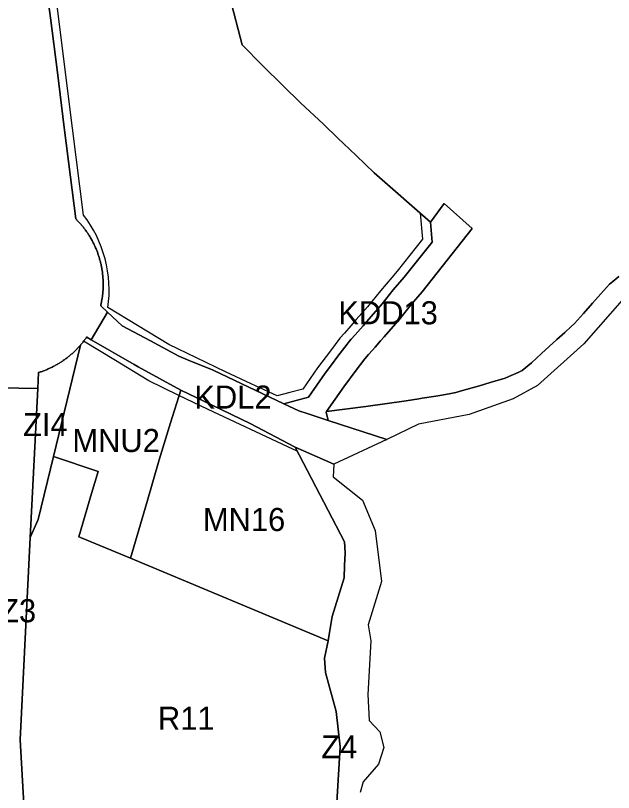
# Model space of a CAD drawing. Extents: x 7439486 to 7443435, y 5551288 to 5554556.
# Drawn here: x 7440797.2 to 7441056.3, y 5551897.3 to 5552233.9 of the extents above; entities that cross this region are included whole.
import ezdxf

# ---------------------------------------------------------------- set-up
doc = ezdxf.new("R2010")
doc.units = 0
for name, color, linetype in [('linie_rozgraniczajace', 7, 'Continuous'), ('linie_zabudowy_nieprzekraczalne', 7, 'Continuous'), ('oznaczenia_przeznaczen', 7, 'Continuous')]:
    doc.layers.add(name, color=color, linetype=linetype)

msp = doc.modelspace()

# ---------------------------------------------------------------- linework, layer by layer
at = {"layer": 'linie_rozgraniczajace'}
for points in [[(7441199.76, 5553005.69), (7441030.31, 5552730.01), (7441018.76, 5552711.22), (7440937.87, 5552579.63), (7440872.68, 5552522.16), (7440861.3, 5552510.94), (7440860.32, 5552509.94), (7440850.87, 5552500.24), (7440841.01, 5552490.47), (7440831.14, 5552480.7), (7440822.38, 5552472.46), (7440813.62, 5552464.22), (7440805.16, 5552456.78), (7440796.71, 5552449.34), (7440788.29, 5552442.28), (7440784.09, 5552438.75), (7440811.19, 5552387.81), (7440863.47, 5552293.77), (7440866.42, 5552287.9), (7440881.12, 5552260.61), (7440890.03, 5552241.86), (7440895.39, 5552221.28), (7440904.26, 5552212.34)], [(7440831.45, 5552134.34), (7440831.28, 5552134.7), (7440831.1, 5552135.06), (7440830.92, 5552135.42), (7440830.74, 5552135.78), (7440830.56, 5552136.13), (7440830.37, 5552136.48), (7440830.17, 5552136.83), (7440829.98, 5552137.18), (7440829.78, 5552137.53), (7440829.58, 5552137.87), (7440829.37, 5552138.22), (7440829.16, 5552138.56), (7440828.95, 5552138.9), (7440828.73, 5552139.23), (7440828.51, 5552139.57), (7440828.29, 5552139.9), (7440828.06, 5552140.23), (7440827.83, 5552140.56), (7440827.6, 5552140.88), (7440827.36, 5552141.2), (7440827.12, 5552141.52), (7440826.88, 5552141.84), (7440826.63, 5552142.16), (7440826.38, 5552142.47), (7440826.13, 5552142.78), (7440825.88, 5552143.09), (7440825.62, 5552143.4), (7440825.36, 5552143.7), (7440825.09, 5552144), (7440824.82, 5552144.3), (7440824.55, 5552144.59), (7440824.28, 5552144.88), (7440824, 5552145.17), (7440823.73, 5552145.46), (7440823.44, 5552145.74), (7440823.33, 5552145.85), (7440821.06, 5552163.89), (7440818.35, 5552185.39), (7440815.35, 5552209.18), (7440812.35, 5552232.97), (7440810.86, 5552244.81)], [(7440810.86, 5552244.81), (7440812.35, 5552232.97), (7440815.35, 5552209.18), (7440818.35, 5552185.39), (7440821.06, 5552163.89), (7440823.33, 5552145.85), (7440823.44, 5552145.74), (7440823.73, 5552145.46), (7440824, 5552145.17), (7440824.28, 5552144.88), (7440824.55, 5552144.59), (7440824.82, 5552144.3), (7440825.09, 5552144), (7440825.36, 5552143.7), (7440825.62, 5552143.4), (7440825.88, 5552143.09), (7440826.13, 5552142.78), (7440826.38, 5552142.47), (7440826.63, 5552142.16), (7440826.88, 5552141.84), (7440827.12, 5552141.52), (7440827.36, 5552141.2), (7440827.6, 5552140.88), (7440827.83, 5552140.56), (7440828.06, 5552140.23), (7440828.29, 5552139.9), (7440828.51, 5552139.57), (7440828.73, 5552139.23), (7440828.95, 5552138.9), (7440829.16, 5552138.56), (7440829.37, 5552138.22), (7440829.58, 5552137.87), (7440829.78, 5552137.53), (7440829.98, 5552137.18), (7440830.17, 5552136.83), (7440830.37, 5552136.48), (7440830.56, 5552136.13), (7440830.74, 5552135.78), (7440830.92, 5552135.42), (7440831.1, 5552135.06), (7440831.28, 5552134.7), (7440831.45, 5552134.34), (7440831.62, 5552133.98), (7440831.78, 5552133.61), (7440831.94, 5552133.25), (7440832.1, 5552132.88), (7440832.25, 5552132.51), (7440832.4, 5552132.14)], [(7441011, 5552077.52), (7441009.36, 5552076.79), (7441002.84, 5552074.87), (7440998.26, 5552073.46), (7440996.72, 5552073.03), (7440990.85, 5552071.38), (7440987.98, 5552070.61), (7440985.82, 5552070.1), (7440981.94, 5552069.36), (7440979.31, 5552068.97), (7440973.47, 5552068.1), (7440971.96, 5552067.8), (7440966.51, 5552067.03), (7440949.03, 5552064.54), (7440931.92, 5552062.32), (7440939.46, 5552073.05), (7440944.87, 5552080.29), (7440948.61, 5552085.24), (7440950.22, 5552087.08), (7440951.85, 5552088.95), (7440953.02, 5552090.28), (7440955.35, 5552092.94), (7440956.93, 5552094.75), (7440963.81, 5552102.61), (7440968.61, 5552108.67), (7440973.37, 5552114.18), (7440995.11, 5552141.6), (7440982.93, 5552152.49), (7440976.95, 5552144.42), (7440952.61, 5552165.83), (7440944.83, 5552173.23), (7440939.3, 5552178.5), (7440937.05, 5552180.63), (7440930.6, 5552186.78), (7440920.74, 5552196.16), (7440913.12, 5552203.41), (7440904.26, 5552212.34), (7440895.39, 5552221.28), (7440890.03, 5552241.86)], [(7440904.26, 5552212.34), (7440913.12, 5552203.41), (7440920.74, 5552196.16), (7440930.6, 5552186.78), (7440937.05, 5552180.63), (7440939.3, 5552178.5), (7440944.83, 5552173.23), (7440952.61, 5552165.83), (7440976.95, 5552144.42), (7440977.69, 5552135.72), (7440965.67, 5552120.55), (7440960.9, 5552115.04), (7440956.12, 5552109.01), (7440949.41, 5552101.34), (7440947.83, 5552099.53), (7440945.5, 5552096.87), (7440944.33, 5552095.53), (7440942.7, 5552093.67), (7440941.77, 5552092.62), (7440940.85, 5552091.56), (7440938.86, 5552088.93), (7440936.87, 5552086.3), (7440934.12, 5552082.61), (7440931.36, 5552078.92), (7440924.12, 5552068.62), (7440913.44, 5552065.74), (7440882.85, 5552080.29), (7440871.72, 5552084.77), (7440867.98, 5552086.26), (7440855.68, 5552092.9), (7440843.38, 5552099.54), (7440837.05, 5552105.45), (7440834.14, 5552108.17), (7440834.23, 5552108.56), (7440834.31, 5552108.95), (7440834.39, 5552109.34), (7440834.47, 5552109.73), (7440834.55, 5552110.13), (7440834.62, 5552110.52), (7440834.69, 5552110.92), (7440834.75, 5552111.31), (7440834.81, 5552111.71), (7440834.86, 5552112.1), (7440834.91, 5552112.5), (7440834.96, 5552112.9), (7440835, 5552113.29), (7440835.04, 5552113.69), (7440835.08, 5552114.09), (7440835.11, 5552114.49), (7440835.13, 5552114.89), (7440835.16, 5552115.29), (7440835.18, 5552115.69), (7440835.19, 5552116.09), (7440835.2, 5552116.49), (7440835.21, 5552116.89), (7440835.21, 5552117.29), (7440835.21, 5552117.69), (7440835.21, 5552118.09), (7440835.2, 5552118.49), (7440835.19, 5552118.89), (7440835.17, 5552119.29), (7440835.15, 5552119.69), (7440835.12, 5552120.09), (7440835.09, 5552120.49), (7440835.06, 5552120.88), (7440835.02, 5552121.28), (7440834.98, 5552121.68), (7440834.94, 5552122.08), (7440834.89, 5552122.48), (7440834.84, 5552122.87), (7440834.78, 5552123.27), (7440834.72, 5552123.66), (7440834.65, 5552124.06), (7440834.59, 5552124.45), (7440834.51, 5552124.85), (7440834.44, 5552125.24), (7440834.36, 5552125.63), (7440834.27, 5552126.02), (7440834.18, 5552126.41), (7440834.09, 5552126.8), (7440834, 5552127.19), (7440833.9, 5552127.58), (7440833.79, 5552127.96), (7440833.68, 5552128.35), (7440833.57, 5552128.73), (7440833.46, 5552129.12), (7440833.34, 5552129.5), (7440833.22, 5552129.88), (7440833.09, 5552130.26), (7440832.96, 5552130.64), (7440832.82, 5552131.01), (7440832.69, 5552131.39), (7440832.55, 5552131.76), (7440832.4, 5552132.14), (7440832.25, 5552132.51), (7440832.1, 5552132.88), (7440831.94, 5552133.25), (7440831.78, 5552133.61), (7440831.62, 5552133.98), (7440831.45, 5552134.34)], [(7440832.4, 5552132.14), (7440832.55, 5552131.76), (7440832.69, 5552131.39), (7440832.82, 5552131.01), (7440832.96, 5552130.64), (7440833.09, 5552130.26), (7440833.22, 5552129.88), (7440833.34, 5552129.5), (7440833.46, 5552129.12), (7440833.57, 5552128.73), (7440833.68, 5552128.35), (7440833.79, 5552127.96), (7440833.9, 5552127.58), (7440834, 5552127.19), (7440834.09, 5552126.8), (7440834.18, 5552126.41), (7440834.27, 5552126.02), (7440834.36, 5552125.63), (7440834.44, 5552125.24), (7440834.51, 5552124.85), (7440834.59, 5552124.45), (7440834.65, 5552124.06), (7440834.72, 5552123.66), (7440834.78, 5552123.27), (7440834.84, 5552122.87), (7440834.89, 5552122.48), (7440834.94, 5552122.08), (7440834.98, 5552121.68), (7440835.02, 5552121.28), (7440835.06, 5552120.88), (7440835.09, 5552120.49), (7440835.12, 5552120.09), (7440835.15, 5552119.69), (7440835.17, 5552119.29), (7440835.19, 5552118.89), (7440835.2, 5552118.49), (7440835.21, 5552118.09), (7440835.21, 5552117.69), (7440835.21, 5552117.29), (7440835.21, 5552116.89), (7440835.2, 5552116.49), (7440835.19, 5552116.09), (7440835.18, 5552115.69), (7440835.16, 5552115.29), (7440835.13, 5552114.89), (7440835.11, 5552114.49), (7440835.08, 5552114.09), (7440835.04, 5552113.69), (7440835, 5552113.29), (7440834.96, 5552112.9), (7440834.91, 5552112.5), (7440834.86, 5552112.1), (7440834.81, 5552111.71), (7440834.75, 5552111.31), (7440834.69, 5552110.92), (7440834.62, 5552110.52), (7440834.55, 5552110.13), (7440834.47, 5552109.73), (7440834.39, 5552109.34), (7440834.31, 5552108.95), (7440834.23, 5552108.56), (7440834.14, 5552108.17), (7440837.05, 5552105.45), (7440830, 5552093.47), (7440828.06, 5552094.58), (7440828.01, 5552094.51), (7440827.78, 5552094.18), (7440827.55, 5552093.86), (7440827.32, 5552093.54), (7440827.08, 5552093.22), (7440826.84, 5552092.9), (7440826.59, 5552092.59), (7440826.34, 5552092.28), (7440826.09, 5552091.97), (7440825.84, 5552091.66), (7440825.58, 5552091.36), (7440825.32, 5552091.05), (7440825.08, 5552090.78), (7440824.81, 5552090.48), (7440824.54, 5552090.18), (7440824.27, 5552089.89), (7440824, 5552089.6), (7440823.72, 5552089.32), (7440823.44, 5552089.04), (7440823.16, 5552088.76), (7440822.87, 5552088.48), (7440822.58, 5552088.2), (7440822.29, 5552087.93), (7440822, 5552087.66), (7440821.7, 5552087.4), (7440821.4, 5552087.14), (7440821.1, 5552086.88), (7440820.79, 5552086.62), (7440820.49, 5552086.37), (7440820.18, 5552086.12), (7440819.86, 5552085.87), (7440819.55, 5552085.62), (7440819.23, 5552085.38), (7440818.91, 5552085.15), (7440818.59, 5552084.91)], [(7440931.77, 5552062.12), (7440931.92, 5552062.32), (7440949.03, 5552064.54), (7440966.51, 5552067.03), (7440971.96, 5552067.8), (7440973.47, 5552068.1), (7440979.31, 5552068.97), (7440981.94, 5552069.36), (7440985.82, 5552070.1), (7440987.98, 5552070.61), (7440990.85, 5552071.38), (7440996.72, 5552073.03), (7440998.26, 5552073.46), (7441002.84, 5552074.87), (7441009.36, 5552076.79), (7441011, 5552077.52), (7441015.07, 5552079.32), (7441016.77, 5552080.14), (7441020.72, 5552083.51), (7441025.11, 5552087.52), (7441031.76, 5552093.58), (7441035.28, 5552096.63), (7441038.02, 5552099.21), (7441039.36, 5552100.48), (7441043.29, 5552104.85), (7441047.16, 5552109.27), (7441053.28, 5552116.09), (7441054.6, 5552117.56), (7441056.02, 5552118.7), (7441058.67, 5552120.82)], [(7441058.67, 5552120.82), (7441056.02, 5552118.7), (7441054.6, 5552117.56), (7441053.28, 5552116.09), (7441047.16, 5552109.27), (7441043.29, 5552104.85), (7441039.36, 5552100.48), (7441038.02, 5552099.21), (7441035.28, 5552096.63), (7441031.76, 5552093.58), (7441025.11, 5552087.52), (7441020.72, 5552083.51), (7441016.77, 5552080.14), (7441015.07, 5552079.32), (7441011, 5552077.52)], [(7441061.04, 5552111.8), (7441043.46, 5552091.62), (7441023.35, 5552073.57), (7441012.83, 5552067.78), (7440993.72, 5552061), (7440971.79, 5552056.9), (7440958.03, 5552050.25), (7440932.72, 5552058.49), (7440931.77, 5552062.12)], [(7440818.59, 5552084.91), (7440818.27, 5552084.68), (7440817.94, 5552084.45), (7440817.61, 5552084.23), (7440817.28, 5552084.01), (7440816.95, 5552083.79), (7440816.61, 5552083.57), (7440816.27, 5552083.36), (7440815.93, 5552083.15), (7440815.59, 5552082.95), (7440815.25, 5552082.75), (7440814.9, 5552082.55), (7440814.56, 5552082.36), (7440814.21, 5552082.17), (7440813.85, 5552081.98), (7440813.5, 5552081.8), (7440813.15, 5552081.62), (7440812.79, 5552081.44), (7440812.43, 5552081.27), (7440812.07, 5552081.1), (7440811.71, 5552080.93), (7440811.34, 5552080.77), (7440810.98, 5552080.61), (7440810.61, 5552080.46), (7440810.24, 5552080.31), (7440809.87, 5552080.16), (7440809.5, 5552080.02), (7440809.13, 5552079.88), (7440808.75, 5552079.74), (7440808.38, 5552079.61), (7440808, 5552079.48), (7440807.62, 5552079.36), (7440807.24, 5552079.23), (7440806.89, 5552072.31), (7440781.88, 5552072.73)], [(7440936.43, 5551892.9), (7440937.85, 5551917.06), (7440936.16, 5551932.33), (7440931.56, 5551949.2), (7440931.14, 5551955.45), (7440932.72, 5551962.93), (7440933.18, 5551965.79), (7440934.41, 5551973.55), (7440937.01, 5551981.91), (7440939.61, 5551990.27), (7440939.79, 5551995.65), (7440939.98, 5552001.04), (7440939.86, 5552003.75), (7440939.77, 5552005.9), (7440929.08, 5552026.38), (7440918.39, 5552046.87), (7440935.14, 5552039.49), (7440934.83, 5552034.11), (7440947.52, 5552023.89), (7440953.08, 5552010.74), (7440955.78, 5551988.68), (7440950.01, 5551969.87), (7440951.13, 5551962.97), (7440949.92, 5551939.68), (7440950.41, 5551928.43), (7440955.1, 5551923.49), (7440956.78, 5551916.8), (7440954.45, 5551909.61), (7440947.8, 5551901.92), (7440946.49, 5551897.2)], [(7440800.76, 5551892.23), (7440799.21, 5551920.11), (7440803.64, 5552007.76), (7440807.02, 5552015.57), (7440813.63, 5552042.85), (7440833.07, 5552036.36), (7440830.18, 5552026.84), (7440824.66, 5552008.11), (7440825.35, 5552007.82), (7440825.36, 5552007.82), (7440847.05, 5551998.75), (7440932.72, 5551962.93), (7440931.14, 5551955.45), (7440931.56, 5551949.2), (7440936.16, 5551932.33), (7440937.85, 5551917.06), (7440936.43, 5551892.9)]]:
    msp.add_lwpolyline(points, dxfattribs=at)
for points in [[(7440913.44, 5552065.74), (7440924.12, 5552068.62), (7440931.36, 5552078.92), (7440934.12, 5552082.61), (7440936.87, 5552086.3), (7440938.86, 5552088.93), (7440940.85, 5552091.56), (7440941.77, 5552092.62), (7440942.7, 5552093.67), (7440944.33, 5552095.53), (7440945.5, 5552096.87), (7440947.83, 5552099.53), (7440949.41, 5552101.34), (7440956.12, 5552109.01), (7440960.9, 5552115.04), (7440965.67, 5552120.55), (7440977.69, 5552135.72), (7440976.95, 5552144.42), (7440982.93, 5552152.49), (7440995.11, 5552141.6), (7440973.37, 5552114.18), (7440968.61, 5552108.67), (7440963.81, 5552102.61), (7440956.93, 5552094.75), (7440955.35, 5552092.94), (7440953.02, 5552090.28), (7440951.85, 5552088.95), (7440950.22, 5552087.08), (7440948.61, 5552085.24), (7440944.87, 5552080.29), (7440939.46, 5552073.05), (7440931.92, 5552062.32), (7440931.77, 5552062.12), (7440932.72, 5552058.49), (7440923.55, 5552061.48), (7440919.93, 5552062.65)], [(7440830, 5552093.47), (7440837.05, 5552105.45), (7440843.38, 5552099.54), (7440855.68, 5552092.9), (7440867.98, 5552086.26), (7440871.72, 5552084.77), (7440882.85, 5552080.29), (7440913.44, 5552065.74), (7440919.93, 5552062.65), (7440923.55, 5552061.48), (7440932.72, 5552058.49), (7440958.03, 5552050.25), (7440935.14, 5552039.49), (7440918.39, 5552046.87), (7440898.89, 5552057.14), (7440882.45, 5552065.06), (7440868.85, 5552071.61), (7440850.42, 5552081.71), (7440848.6, 5552082.76)], [(7440813.63, 5552042.85), (7440825.32, 5552091.05), (7440825.58, 5552091.36), (7440825.84, 5552091.66), (7440826.09, 5552091.97), (7440826.34, 5552092.28), (7440826.59, 5552092.59), (7440826.84, 5552092.9), (7440827.08, 5552093.22), (7440827.32, 5552093.54), (7440827.55, 5552093.86), (7440827.78, 5552094.18), (7440828.01, 5552094.51), (7440828.06, 5552094.58), (7440830, 5552093.47), (7440848.6, 5552082.76), (7440850.42, 5552081.71), (7440868.85, 5552071.61), (7440864.43, 5552057.43), (7440860, 5552043.26), (7440859.4, 5552041.35), (7440854.2, 5552023.4), (7440847.05, 5551998.75), (7440825.36, 5552007.82), (7440825.35, 5552007.82), (7440824.66, 5552008.11), (7440830.18, 5552026.84), (7440833.07, 5552036.36)], [(7440803.64, 5552007.76), (7440806.89, 5552072.31), (7440807.24, 5552079.23), (7440807.62, 5552079.36), (7440808, 5552079.48), (7440808.38, 5552079.61), (7440808.75, 5552079.74), (7440809.13, 5552079.88), (7440809.5, 5552080.02), (7440809.87, 5552080.16), (7440810.24, 5552080.31), (7440810.61, 5552080.46), (7440810.98, 5552080.61), (7440811.34, 5552080.77), (7440811.71, 5552080.93), (7440812.07, 5552081.1), (7440812.43, 5552081.27), (7440812.79, 5552081.44), (7440813.15, 5552081.62), (7440813.5, 5552081.8), (7440813.85, 5552081.98), (7440814.21, 5552082.17), (7440814.56, 5552082.36), (7440814.9, 5552082.55), (7440815.25, 5552082.75), (7440815.59, 5552082.95), (7440815.93, 5552083.15), (7440816.27, 5552083.36), (7440816.61, 5552083.57), (7440816.95, 5552083.79), (7440817.28, 5552084.01), (7440817.61, 5552084.23), (7440817.94, 5552084.45), (7440818.27, 5552084.68), (7440818.59, 5552084.91), (7440818.91, 5552085.15), (7440819.23, 5552085.38), (7440819.55, 5552085.62), (7440819.86, 5552085.87), (7440820.18, 5552086.12), (7440820.49, 5552086.37), (7440820.79, 5552086.62), (7440821.1, 5552086.88), (7440821.4, 5552087.14), (7440821.7, 5552087.4), (7440822, 5552087.66), (7440822.29, 5552087.93), (7440822.58, 5552088.2), (7440822.87, 5552088.48), (7440823.16, 5552088.76), (7440823.44, 5552089.04), (7440823.72, 5552089.32), (7440824, 5552089.6), (7440824.27, 5552089.89), (7440824.54, 5552090.18), (7440824.81, 5552090.48), (7440825.08, 5552090.78), (7440825.32, 5552091.05), (7440813.63, 5552042.85), (7440807.02, 5552015.57)], [(7440774.18, 5551920.04), (7440781.88, 5552072.73), (7440806.89, 5552072.31), (7440803.64, 5552007.76), (7440799.21, 5551920.11), (7440800.76, 5551892.23), (7440801.61, 5551877.02), (7440776.82, 5551882.03), (7440776.29, 5551882.14), (7440775.35, 5551899.06)], [(7440847.05, 5551998.75), (7440854.2, 5552023.4), (7440859.4, 5552041.35), (7440860, 5552043.26), (7440864.43, 5552057.43), (7440868.85, 5552071.61), (7440882.45, 5552065.06), (7440898.89, 5552057.14), (7440918.39, 5552046.87), (7440929.08, 5552026.38), (7440939.77, 5552005.9), (7440939.86, 5552003.75), (7440939.98, 5552001.04), (7440939.79, 5551995.65), (7440939.61, 5551990.27), (7440937.01, 5551981.91), (7440934.41, 5551973.55), (7440933.18, 5551965.79), (7440932.72, 5551962.93)]]:
    msp.add_lwpolyline(points, close=True, dxfattribs=at)
at = {"layer": 'linie_zabudowy_nieprzekraczalne'}
for points in [[(7440972.6, 5552148.24), (7440973.57, 5552136.96), (7440962.58, 5552123.11), (7440960.2, 5552120.35), (7440955.43, 5552114.58), (7440949.72, 5552107.77), (7440944.82, 5552102.17), (7440942.49, 5552099.51), (7440939.69, 5552096.3), (7440937.75, 5552094.09), (7440933.67, 5552088.7), (7440928.13, 5552081.27), (7440921.68, 5552072.1), (7440916.11, 5552070.6), (7440910.54, 5552069.1), (7440899.39, 5552074.3), (7440888.24, 5552079.51), (7440875.61, 5552085.62), (7440863.63, 5552091.37), (7440850.13, 5552099.61), (7440837.27, 5552107.46), (7440837.58, 5552110.03), (7440837.75, 5552112.65), (7440837.8, 5552115.29), (7440837.72, 5552117.94), (7440837.5, 5552120.6), (7440837.14, 5552123.26), (7440836.65, 5552125.9), (7440836.03, 5552128.52), (7440835.27, 5552131.1), (7440834.39, 5552133.63), (7440833.38, 5552136.12), (7440832.25, 5552138.54), (7440831, 5552140.88), (7440829.65, 5552143.15), (7440828.2, 5552145.33), (7440826.66, 5552147.42), (7440820.32, 5552197.72), (7440815.07, 5552239.39)], [(7440919.29, 5552045.16), (7440915.28, 5552047.02), (7440880.63, 5552063.2), (7440867.76, 5552069.42), (7440855.02, 5552075.59), (7440854.25, 5552076.01), (7440840.5, 5552084.4), (7440826.75, 5552092.79)]]:
    msp.add_lwpolyline(points, dxfattribs=at)

# ---------------------------------------------------------------- texts
at = {"layer": 'oznaczenia_przeznaczen'}
for s, p in [('KDD13', (7440937.1, 5552100.12)), ('KDL2', (7440874.71, 5552063.61)), ('ZI4', (7440800.49, 5552051.71)), ('MNU2', (7440821.86, 5552044.79)), ('MN16', (7440878.42, 5552010.56)), ('KDZ3', (7440771.99, 5551971.04)), ('R11', (7440858.94, 5551924.43)), ('Z4', (7440929.66, 5551912.06))]:
    msp.add_text(s, height=10, dxfattribs=at).set_placement(p)

doc.saveas('drawing.dxf')
